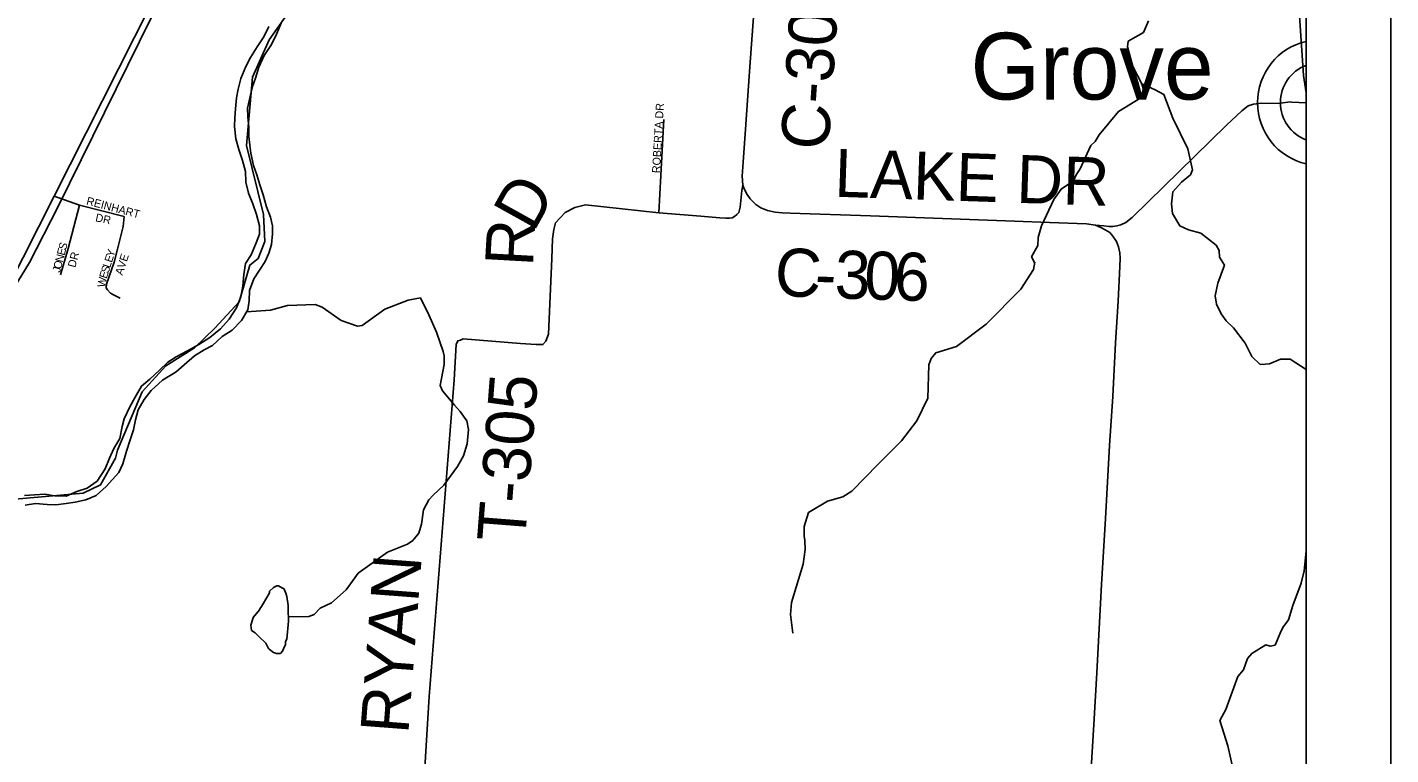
# Model space of a CAD drawing. Extents: x 0 to 40.4, y 0 to 22.
# Drawn here: x 7.886 to 9.5, y 19.2 to 20.061 of the extents above; entities that cross this region are included whole.
import ezdxf

# ---------------------------------------------------------------- set-up
doc = ezdxf.new("R2010")
doc.units = 0
for name, color, linetype in [('GM_X_Corporation', 7, 'Continuous'), ('GM_X_County_Road', 7, 'Continuous'), ('GM_X_County_Road_Text', 7, 'Continuous'), ('GM_X_Major_River', 7, 'Continuous'), ('GM_X_Minor_Lake', 7, 'Continuous'), ('GM_X_Minor_River', 7, 'Continuous'), ('GM_X_State_Route', 7, 'Continuous'), ('GM_X_Township', 7, 'Continuous'), ('GM_X_Township_Road', 7, 'Continuous'), ('GM_X_Township_Road_Text', 7, 'Continuous'), ('GM_X_Township_Subdivision', 7, 'Continuous'), ('GM_X_Township_Subdivision_Text', 7, 'Continuous'), ('GM_X_Unincorporated', 7, 'Continuous'), ('GM_X_Unincorporated_Text', 7, 'Continuous'), ('SH_Data', 7, 'Continuous')]:
    doc.layers.add(name, color=color, linetype=linetype)

msp = doc.modelspace()

# ---------------------------------------------------------------- linework, layer by layer
at = {"layer": 'GM_X_Corporation'}
msp.add_lwpolyline([(7.8299, 19.6864), (7.8892, 19.7826), (7.9226, 19.848), (8.047, 20.1003)], dxfattribs=at)
at = {"layer": 'GM_X_County_Road'}
for points in [[(8.7332, 19.8739), (8.7326, 19.8846), (8.7336, 19.9013), (8.7368, 19.9458), (8.741, 20.0086), (8.7466, 20.0839), (8.75, 20.1479), (8.7555, 20.2239), (8.7628, 20.3262)], [(8.7332, 19.8739), (8.7349, 19.8697), (8.7384, 19.8631), (8.7419, 19.8578), (8.7486, 19.8512), (8.7545, 19.8471), (8.7624, 19.8441), (8.7715, 19.8421), (8.7797, 19.8413), (8.7892, 19.8407), (8.8844, 19.8377), (9.0546, 19.8316), (9.0962, 19.83), (9.1398, 19.8281), (9.1507, 19.8267)], [(9.1449, 19.1707), (9.1485, 19.2357), (9.1522, 19.2969), (9.1577, 19.4013), (9.1625, 19.4794), (9.1673, 19.5658), (9.1711, 19.6239), (9.1744, 19.6876), (9.1773, 19.7369), (9.1794, 19.7777), (9.1799, 19.7878), (9.1793, 19.794), (9.1779, 19.8009), (9.1754, 19.8072), (9.1712, 19.8135), (9.1677, 19.818), (9.1621, 19.8212), (9.1571, 19.8241), (9.1507, 19.8267)]]:
    msp.add_lwpolyline(points, dxfattribs=at)
at = {"layer": 'GM_X_Major_River'}
for points in [[(8.1724, 20.0617), (8.1663, 20.0496), (8.1587, 20.0379), (8.1507, 20.025), (8.145, 20.0144), (8.1393, 20.0004), (8.1359, 19.9876), (8.1339, 19.9773), (8.1328, 19.9645), (8.132, 19.9539), (8.1316, 19.9433), (8.1334, 19.9289), (8.1368, 19.9163), (8.1413, 19.9031), (8.1447, 19.8902), (8.1451, 19.8777), (8.1481, 19.8644), (8.1534, 19.8519), (8.1579, 19.8394), (8.1612, 19.8261), (8.1612, 19.8159), (8.1574, 19.8057), (8.1513, 19.7917), (8.1449, 19.7814)], [(8.168, 19.7837), (8.1725, 19.7935), (8.1756, 19.8038), (8.1768, 19.8166), (8.1768, 19.8261), (8.1742, 19.836), (8.1696, 19.8485), (8.1655, 19.8625), (8.1617, 19.8746), (8.158, 19.8864), (8.1542, 19.8974), (8.1512, 19.9118), (8.1497, 19.9212), (8.1486, 19.9315), (8.1486, 19.9425), (8.1475, 19.955), (8.1472, 19.9652), (8.1502, 19.9788), (8.1529, 19.9906), (8.1567, 20.0008), (8.1606, 20.0137), (8.167, 20.0273), (8.1754, 20.0405), (8.1815, 20.0526), (8.1868, 20.0659)], [(7.9324, 19.4972), (7.943, 19.499), (7.9558, 19.5016), (7.9679, 19.5069), (7.9797, 19.5174), (7.9949, 19.5341), (7.9995, 19.5443), (8.0041, 19.5591), (8.0083, 19.5727), (8.0121, 19.5844), (8.0144, 19.5962), (8.0179, 19.6083), (8.0248, 19.6204), (8.0331, 19.631), (8.0464, 19.6431), (8.0627, 19.6532), (8.0722, 19.6615), (8.0843, 19.6721), (8.0957, 19.6793), (8.1056, 19.6842), (8.117, 19.6951), (8.1291, 19.7023), (8.1401, 19.714), (8.1473, 19.7265), (8.1489, 19.7371), (8.1493, 19.7492), (8.1547, 19.7632), (8.168, 19.7837)], [(8.1449, 19.7814), (8.1426, 19.7682), (8.1414, 19.7545), (8.1391, 19.742), (8.1341, 19.7288), (8.1254, 19.7156), (8.1151, 19.7042), (8.1026, 19.6936), (8.0897, 19.6854), (8.076, 19.6778), (8.0628, 19.6707), (8.0529, 19.6646), (8.043, 19.6552), (8.0317, 19.6443), (8.0218, 19.6363), (8.0142, 19.6231), (8.0077, 19.6117), (8.0012, 19.5977), (7.9989, 19.5883), (7.9962, 19.5743), (7.989, 19.5625), (7.9836, 19.5508), (7.9787, 19.5383), (7.9691, 19.5239), (7.9574, 19.5156), (7.9453, 19.5115), (7.9324, 19.5059), (7.9188, 19.5063), (7.9071, 19.5083), (7.895, 19.5075), (7.8832, 19.5068)], [(7.8839, 19.4955), (7.8961, 19.4973), (7.91, 19.4961), (7.9202, 19.4957), (7.9324, 19.4972)]]:
    msp.add_lwpolyline(points, dxfattribs=at)
at = {"layer": 'GM_X_Minor_Lake'}
for points in [[(8.1956, 19.3581), (8.1952, 19.3721), (8.1952, 19.3766), (8.1937, 19.3873), (8.1926, 19.3914), (8.19, 19.3967), (8.1885, 19.3971), (8.1836, 19.3998), (8.1817, 19.3998), (8.1779, 19.3979), (8.1733, 19.3934), (8.1733, 19.3918), (8.1714, 19.3888), (8.1711, 19.3881), (8.1635, 19.3756), (8.1616, 19.3725), (8.1612, 19.3714), (8.154, 19.3623), (8.1532, 19.3597), (8.1509, 19.3532), (8.1517, 19.3471), (8.1562, 19.3441)], [(8.1562, 19.3441), (8.163, 19.3376), (8.1664, 19.3346), (8.1687, 19.3319), (8.1721, 19.3259), (8.1728, 19.3251), (8.1777, 19.3209), (8.1815, 19.3198), (8.186, 19.3198), (8.1887, 19.3224), (8.1898, 19.3255), (8.1921, 19.3304), (8.1921, 19.3342), (8.1936, 19.3368), (8.1956, 19.3581)]]:
    msp.add_lwpolyline(points, dxfattribs=at)
at = {"layer": 'GM_X_Minor_River'}
for points in [[(9.0787, 19.7819), (9.075, 19.7894), (9.0822, 19.8027), (9.0829, 19.8122), (9.0867, 19.8258), (9.1015, 19.8569), (9.1098, 19.8694), (9.1246, 19.8793), (9.1276, 19.8861), (9.1325, 19.8933), (9.145, 19.921), (9.1503, 19.9256), (9.1548, 19.9336), (9.1779, 19.9613), (9.2044, 19.9772), (9.2082, 19.984), (9.2054, 19.994), (9.1949, 20.0143), (9.1885, 20.0378), (9.1892, 20.0443), (9.2074, 20.0545), (9.2134, 20.0686)], [(9.3031, 19.7795), (9.2975, 19.7889), (9.2971, 19.7969), (9.2933, 19.8029), (9.2751, 19.8173), (9.2607, 19.8211), (9.2504, 19.826), (9.2417, 19.8404), (9.2406, 19.8518), (9.2421, 19.8662), (9.2523, 19.8776), (9.2629, 19.8863), (9.2655, 19.892), (9.2598, 19.917), (9.242, 19.9534), (9.2313, 19.9814), (9.2211, 19.9867), (9.2048, 19.9943)], [(9.0789, 19.7829), (9.0774, 19.7742), (9.0622, 19.7511), (9.0213, 19.7095), (8.9861, 19.683), (8.9615, 19.6755), (8.9562, 19.669), (8.9535, 19.6615), (8.9523, 19.622), (8.939, 19.5951), (8.9212, 19.5713), (8.8935, 19.5437), (8.8621, 19.5119), (8.8515, 19.5054), (8.8333, 19.5002), (8.811, 19.4866), (8.8057, 19.4703), (8.806, 19.4585), (8.8068, 19.4536), (8.8071, 19.443), (8.8048, 19.4255), (8.7907, 19.3801), (8.7896, 19.366), (8.7926, 19.344)], [(9.4, 19.6559), (9.3811, 19.6683), (9.3694, 19.6683), (9.3566, 19.6626), (9.3513, 19.6622), (9.3456, 19.6619), (9.3358, 19.6714), (9.3279, 19.6869), (9.3139, 19.7052), (9.3052, 19.7135), (9.2992, 19.7219), (9.2939, 19.7332), (9.2924, 19.7431), (9.2955, 19.7579), (9.3031, 19.7795)], [(8.1459, 19.724), (8.1744, 19.7262), (8.1944, 19.7315), (8.2273, 19.733), (8.2356, 19.7295), (8.2579, 19.714), (8.2772, 19.7071), (8.2829, 19.7078), (8.3097, 19.7271), (8.3374, 19.7381), (8.3517, 19.7407), (8.3615, 19.7206), (8.3706, 19.7001), (8.3785, 19.6773), (8.38, 19.672), (8.3799, 19.6618), (8.375, 19.6368), (8.378, 19.6307), (8.3919, 19.6136), (8.3987, 19.606), (8.4066, 19.595), (8.4085, 19.5848), (8.407, 19.5681), (8.4028, 19.5537), (8.3956, 19.5412), (8.3793, 19.5192), (8.3668, 19.5071), (8.3615, 19.5018), (8.3554, 19.4897), (8.3531, 19.473), (8.35, 19.4624), (8.3428, 19.4537), (8.3364, 19.4492), (8.3126, 19.4397), (8.2781, 19.4148), (8.2743, 19.4095), (8.2637, 19.3951), (8.2467, 19.3796), (8.233, 19.3735), (8.2258, 19.366), (8.2198, 19.3637), (8.1954, 19.3634)], [(9.4, 19.4415), (9.3977, 19.4176), (9.3942, 19.4032), (9.384, 19.3767), (9.379, 19.3596), (9.3722, 19.3506), (9.3691, 19.3437), (9.3631, 19.3297), (9.3574, 19.3286), (9.3521, 19.3301), (9.3355, 19.3199), (9.3305, 19.3139), (9.3256, 19.3006), (9.3191, 19.2926), (9.3047, 19.2536), (9.2979, 19.2404), (9.3073, 19.2104), (9.3177, 19.1634)]]:
    msp.add_lwpolyline(points, dxfattribs=at)
at = {"layer": 'GM_X_State_Route'}
msp.add_lwpolyline([(7.4592, 19.3188), (7.4821, 19.3405), (7.5133, 19.3667), (7.6013, 19.4547), (7.7521, 19.6099), (7.7893, 19.648), (7.8147, 19.6742), (7.8277, 19.69), (7.8409, 19.7099), (7.8818, 19.7884), (7.9183, 19.8609), (8.0322, 20.0867), (8.0488, 20.1183), (8.0619, 20.1422), (8.13, 20.2571), (8.1543, 20.2979), (8.1577, 20.3035)], dxfattribs=at)
at = {"layer": 'GM_X_Township'}
msp.add_lwpolyline([(7.8449, 19.4999), (7.9526, 19.5095), (7.9733, 19.5194), (7.9907, 19.5508), (7.9932, 19.5603), (8.0225, 19.6295), (8.0505, 19.6603), (8.0843, 19.6817), (8.1086, 19.7049), (8.1374, 19.7361), (8.15, 19.7795), (8.1596, 19.7872), (8.1678, 19.8072), (8.1662, 19.8392), (8.1461, 19.9211), (8.1529, 20.002), (8.1727, 20.0459), (8.1943, 20.0769)], dxfattribs=at)
at = {"layer": 'GM_X_Township_Road'}
for points in [[(9.4, 19.9831), (9.3966, 20.0037), (9.3875, 20.1454), (9.3849, 20.209), (9.3815, 20.2345), (9.3742, 20.2445), (9.369, 20.2549), (9.3647, 20.2739), (9.3624, 20.3144), (9.354, 20.4303), (9.3537, 20.4339)], [(9.1507, 19.8267), (9.1605, 19.826), (9.1664, 19.8253), (9.1713, 19.8251), (9.1759, 19.8258), (9.1807, 19.8272), (9.1865, 19.8298), (9.1939, 19.8358), (9.3056, 19.9451), (9.3236, 19.9621), (9.3314, 19.9681), (9.3377, 19.97), (9.3472, 19.9709), (9.3667, 19.9706), (9.3809, 19.9725), (9.3827, 19.9724)], [(9.3827, 19.9724), (9.4, 19.9714)], [(8.7332, 19.8739), (8.7321, 19.8676), (8.7303, 19.8481), (8.7287, 19.8418), (8.7263, 19.8392), (8.7235, 19.8369), (8.7207, 19.8355), (8.7175, 19.835), (8.7132, 19.8348), (8.7061, 19.8352), (8.6837, 19.8372), (8.634, 19.8411), (8.547, 19.8506), (8.5346, 19.8477), (8.5229, 19.8417), (8.5115, 19.8294), (8.5098, 19.8215), (8.508, 19.8105), (8.5073, 19.7871), (8.5032, 19.6978), (8.5, 19.6894), (8.4966, 19.6854), (8.4889, 19.6854), (8.4702, 19.6867), (8.4025, 19.6922), (8.3992, 19.6908), (8.396, 19.6899), (8.3941, 19.6854), (8.3916, 19.6438), (8.362, 19.2688), (8.3417, 18.9317)]]:
    msp.add_lwpolyline(points, dxfattribs=at)
at = {"layer": 'GM_X_Township_Subdivision'}
for points in [[(8.634, 19.8411), (8.6399, 19.9517)], [(7.9183, 19.8609), (7.9483, 19.8505), (8.001, 19.837)], [(7.9258, 19.768), (7.9348, 19.7991), (7.9483, 19.8505)], [(7.9964, 19.7405), (7.9887, 19.7441), (7.9848, 19.7464), (7.9813, 19.75), (7.9799, 19.7524), (7.9801, 19.757), (7.9892, 19.7829), (7.9933, 19.7983), (7.9999, 19.8252), (8.001, 19.837)]]:
    msp.add_lwpolyline(points, dxfattribs=at)
at = {"layer": 'GM_X_Unincorporated'}
for p, q in [((9.4, 19.8992), (9.4, 20.0442)), ((9.4, 19.9276), (9.4, 20.0158))]:
    msp.add_line(p, q, dxfattribs=at)
for radius, start, end in [(0.0744, 102.9978, 257.0022), (0.0472, 110.7817, 249.2183)]:
    msp.add_arc((9.4167, 19.9717), radius, start, end, dxfattribs=at)
at = {"layer": 'SH_Data'}
for p, q in [((9.5, 21), (9.5, 14)), ((9.4, 20.9), (9.4, 14.1))]:
    msp.add_line(p, q, dxfattribs=at)

# ---------------------------------------------------------------- texts
at = {"layer": 'GM_X_County_Road_Text'}
for s, height, rotation, p in [('C-305', 0.05682, 86.186, (8.8346, 19.9147)), ('LAKE DR', 0.05682, 358.0853, (8.8411, 19.8604)), ('C', 0.0568, 356.7197, (8.7699, 19.7437)), ('3', 0.0568, 358.2229, (8.8414, 19.7402)), ('0', 0.0568, 358.2832, (8.8764, 19.7391)), ('6', 0.0568, 358.2987, (8.9114, 19.738)), ('-', 0.0568, 358.0796, (8.8179, 19.7409))]:
    msp.add_text(s, height=height, rotation=rotation, dxfattribs=at).set_placement(p)
at = {"layer": 'GM_X_Township_Road_Text'}
for s, height, rotation, p in [('D', 0.0568, 60.9139, (8.4855, 19.8172)), ('R', 0.0568, 86.8057, (8.4848, 19.7771)), ('T-305', 0.05682, 85.4937, (8.4753, 19.4502)), ('RYAN', 0.05682, 85.64, (8.3373, 19.2238))]:
    msp.add_text(s, height=height, rotation=rotation, dxfattribs=at).set_placement(p)
at = {"layer": 'GM_X_Township_Subdivision_Text'}
for s, rotation, p in [('ROBERTA DR', 86.7474, (8.6352, 19.888)), ('REINHART', 345.1755, (7.9557, 19.8513)), ('DR', 348.105, (7.9665, 19.8314)), ('E', 75.4559, (7.9305, 19.7902)), ('S', 73.5179, (7.9321, 19.7966)), ('Y', 71.8898, (7.9886, 19.7882)), ('O', 75.4389, (7.9263, 19.774)), ('N', 75.4538, (7.9284, 19.7821)), ('DR', 75.2649, (7.9433, 19.7759)), ('L', 71.8847, (7.9844, 19.7755)), ('E', 71.897, (7.9865, 19.7818)), ('AVE', 72.176, (7.9991, 19.7668)), ('J', 75.4655, (7.9252, 19.77)), ('W', 79.465, (7.9785, 19.7525)), ('E', 72.5759, (7.9804, 19.7628)), ('S', 71.8847, (7.9824, 19.7691))]:
    msp.add_text(s, height=0.00947, rotation=rotation, dxfattribs=at).set_placement(p)
at = {"layer": 'GM_X_Unincorporated_Text'}
msp.add_text('Grove', height=0.07898, rotation=0, dxfattribs=at).set_placement((9.0028, 19.9754))

doc.saveas('drawing.dxf')
